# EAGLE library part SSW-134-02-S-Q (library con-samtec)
THROUGH-HOLE .025" SQ POST SOCKET Source: Samtec SSW.pdf
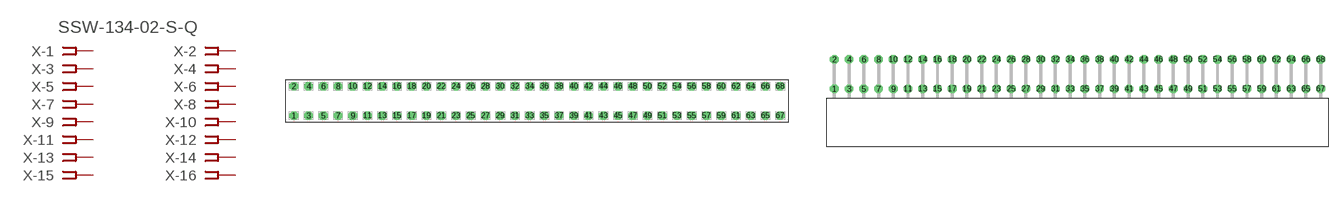
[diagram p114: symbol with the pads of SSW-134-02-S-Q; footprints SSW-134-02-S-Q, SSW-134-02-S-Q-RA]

Designator prefix X; gates -1=FPINV -2=FPIN -3=FPIN -4=FPIN -5=FPIN -6=FPIN -7=FPIN -8=FPIN -9=FPIN -10=FPIN -11=FPIN -12=FPIN -13=FPIN -14=FPIN -15=FPIN -16=FPIN -17=FPIN -18=FPIN -19=FPIN -20=FPIN -21=FPIN -22=FPIN -23=FPIN -24=FPIN -25=FPIN -26=FPIN -27=FPIN -28=FPIN -29=FPIN -30=FPIN -31=FPIN -32=FPIN -33=FPIN -34=FPIN -35=FPIN -36=FPIN -37=FPIN -38=FPIN -39=FPIN -40=FPIN -41=FPIN -42=FPIN -43=FPIN -44=FPIN -45=FPIN -46=FPIN -47=FPIN -48=FPIN -49=FPIN -50=FPIN -51=FPIN -52=FPIN -53=FPIN -54=FPIN -55=FPIN -56=FPIN -57=FPIN -58=FPIN -59=FPIN -60=FPIN -61=FPIN -62=FPIN -63=FPIN -64=FPIN -65=FPIN -66=FPIN -67=FPIN -68=FPIN

## SSW-134-02-S-Q (MPN: SSW-134-02-S-Q; OC_FARNELL: unknown; OC_NEWARK: 83P0619)  [SSW-134-02-S-Q]
1  -1:1  pas
2  -2:1  pas
3  -3:1  pas
4  -4:1  pas
5  -5:1  pas
6  -6:1  pas
7  -7:1  pas
8  -8:1  pas
9  -9:1  pas
10  -10:1  pas
11  -11:1  pas
12  -12:1  pas
13  -13:1  pas
14  -14:1  pas
15  -15:1  pas
16  -16:1  pas
17  -17:1  pas
18  -18:1  pas
19  -19:1  pas
20  -20:1  pas
21  -21:1  pas
22  -22:1  pas
23  -23:1  pas
24  -24:1  pas
25  -25:1  pas
26  -26:1  pas
27  -27:1  pas
28  -28:1  pas
29  -29:1  pas
30  -30:1  pas
31  -31:1  pas
32  -32:1  pas
33  -33:1  pas
34  -34:1  pas
35  -35:1  pas
36  -36:1  pas
37  -37:1  pas
38  -38:1  pas
39  -39:1  pas
40  -40:1  pas
41  -41:1  pas
42  -42:1  pas
43  -43:1  pas
44  -44:1  pas
45  -45:1  pas
46  -46:1  pas
47  -47:1  pas
48  -48:1  pas
49  -49:1  pas
50  -50:1  pas
51  -51:1  pas
52  -52:1  pas
53  -53:1  pas
54  -54:1  pas
55  -55:1  pas
56  -56:1  pas
57  -57:1  pas
58  -58:1  pas
59  -59:1  pas
60  -60:1  pas
61  -61:1  pas
62  -62:1  pas
63  -63:1  pas
64  -64:1  pas
65  -65:1  pas
66  -66:1  pas
67  -67:1  pas
68  -68:1  pas

## SSW-134-02-S-QRA (MPN: SSW-134-02-S-Q-RA; OC_FARNELL: unknown; OC_NEWARK: 83P0620)  [SSW-134-02-S-Q-RA]
Pads as for SSW-134-02-S-Q

## Footprint SSW-134-02-S-Q (pad centres in mm)
THROUGH-HOLE .025" SQ POST SOCKET Source: Samtec SSW.pdf
drill 1 pad 1.5 octagon: 1 -41.91,-2.54; 2 -41.91,2.54; 3 -39.37,-2.54; 4 -39.37,2.54; 5 -36.83,-2.54; 6 -36.83,2.54; 7 -34.29,-2.54; 8 -34.29,2.54; 9 -31.75,-2.54; 10 -31.75,2.54; 11 -29.21,-2.54; 12 -29.21,2.54; 13 -26.67,-2.54; 14 -26.67,2.54; 15 -24.13,-2.54; 16 -24.13,2.54; 17 -21.59,-2.54; 18 -21.59,2.54; 19 -19.05,-2.54; 20 -19.05,2.54; 21 -16.51,-2.54; 22 -16.51,2.54; 23 -13.97,-2.54; 24 -13.97,2.54; 25 -11.43,-2.54; 26 -11.43,2.54; 27 -8.89,-2.54; 28 -8.89,2.54; 29 -6.35,-2.54; 30 -6.35,2.54; 31 -3.81,-2.54; 32 -3.81,2.54; 33 -1.27,-2.54; 34 -1.27,2.54; 35 1.27,-2.54; 36 1.27,2.54; 37 3.81,-2.54; 38 3.81,2.54; 39 6.35,-2.54; 40 6.35,2.54; 41 8.89,-2.54; 42 8.89,2.54; 43 11.43,-2.54; 44 11.43,2.54; 45 13.97,-2.54; 46 13.97,2.54; 47 16.51,-2.54; 48 16.51,2.54; 49 19.05,-2.54; 50 19.05,2.54; 51 21.59,-2.54; 52 21.59,2.54; 53 24.13,-2.54; 54 24.13,2.54; 55 26.67,-2.54; 56 26.67,2.54; 57 29.21,-2.54; 58 29.21,2.54; 59 31.75,-2.54; 60 31.75,2.54; 61 34.29,-2.54; 62 34.29,2.54; 63 36.83,-2.54; 64 36.83,2.54; 65 39.37,-2.54; 66 39.37,2.54; 67 41.91,-2.54; 68 41.91,2.54

## Footprint SSW-134-02-S-Q-RA (pad centres in mm)
THROUGH-HOLE .025" SQ POST SOCKET Source: Samtec SSW.pdf
drill 1 pad 1.5 octagon: 1 -41.91,1.524; 2 -41.91,6.604; 3 -39.37,1.524; 4 -39.37,6.604; 5 -36.83,1.524; 6 -36.83,6.604; 7 -34.29,1.524; 8 -34.29,6.604; 9 -31.75,1.524; 10 -31.75,6.604; 11 -29.21,1.524; 12 -29.21,6.604; 13 -26.67,1.524; 14 -26.67,6.604; 15 -24.13,1.524; 16 -24.13,6.604; 17 -21.59,1.524; 18 -21.59,6.604; 19 -19.05,1.524; 20 -19.05,6.604; 21 -16.51,1.524; 22 -16.51,6.604; 23 -13.97,1.524; 24 -13.97,6.604; 25 -11.43,1.524; 26 -11.43,6.604; 27 -8.89,1.524; 28 -8.89,6.604; 29 -6.35,1.524; 30 -6.35,6.604; 31 -3.81,1.524; 32 -3.81,6.604; 33 -1.27,1.524; 34 -1.27,6.604; 35 1.27,1.524; 36 1.27,6.604; 37 3.81,1.524; 38 3.81,6.604; 39 6.35,1.524; 40 6.35,6.604; 41 8.89,1.524; 42 8.89,6.604; 43 11.43,1.524; 44 11.43,6.604; 45 13.97,1.524; 46 13.97,6.604; 47 16.51,1.524; 48 16.51,6.604; 49 19.05,1.524; 50 19.05,6.604; 51 21.59,1.524; 52 21.59,6.604; 53 24.13,1.524; 54 24.13,6.604; 55 26.67,1.524; 56 26.67,6.604; 57 29.21,1.524; 58 29.21,6.604; 59 31.75,1.524; 60 31.75,6.604; 61 34.29,1.524; 62 34.29,6.604; 63 36.83,1.524; 64 36.83,6.604; 65 39.37,1.524; 66 39.37,6.604; 67 41.91,1.524; 68 41.91,6.604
